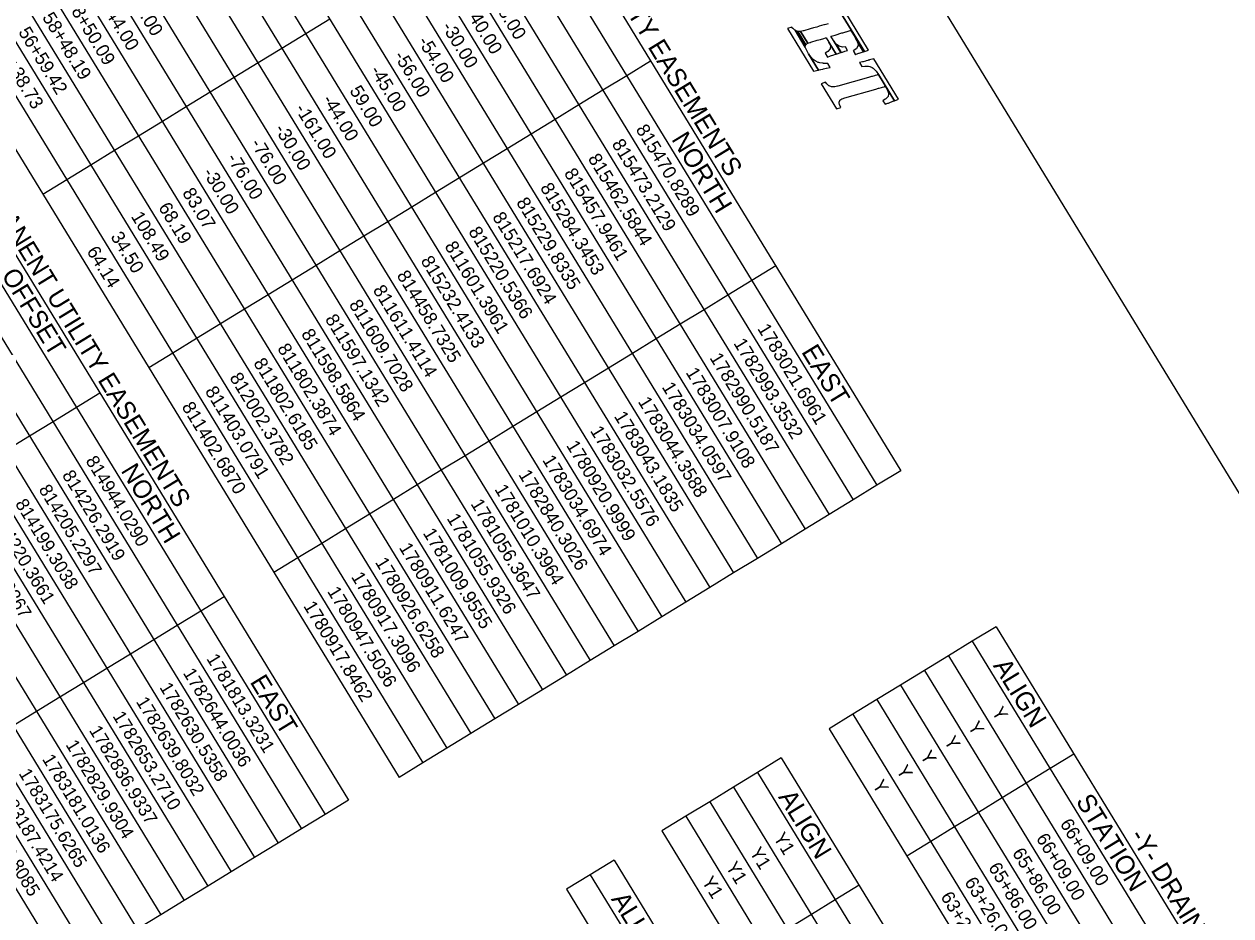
# Model space of a CAD drawing. Extents: x 1753086 to 1770987, y 792577 to 812636.
# Drawn here: x 1764623 to 1768654, y 800134 to 803112 of the extents above; entities that cross this region are included whole.
import ezdxf

# ---------------------------------------------------------------- set-up
doc = ezdxf.new("R2010")
doc.units = 0
for name, color, linetype in [('CTL Sheet Border CELL', 7, 'Continuous'), ('CTL Sheet Notes CELL', 7, 'Continuous'), ('CTL Sheet Table Cell', 7, 'Continuous'), ('CTL Sheet Text', 7, 'Continuous'), ('Sheet Data Field CELL', 7, 'Continuous')]:
    doc.layers.add(name, color=color, linetype=linetype)

msp = doc.modelspace()

# ---------------------------------------------------------------- linework, layer by layer
at = {"layer": 'CTL Sheet Border CELL'}
msp.add_lwpolyline([(1770671.7, 798289.4), (1762511, 811645.8), (1753161.6, 805933.4), (1761322.3, 792577)], close=True, dxfattribs=at)
at = {"layer": 'CTL Sheet Table Cell'}
for p, q in [((1765751, 804567), (1767551.4, 801620.3)), ((1765671.2, 804518.2), (1767471.6, 801571.5)), ((1765591.4, 804469.4), (1767391.8, 801522.7)), ((1765511.6, 804420.7), (1767312, 801474)), ((1765431.7, 804371.9), (1767232.2, 801425.2)), ((1765351.9, 804323.1), (1767152.4, 801376.4)), ((1765272.1, 804274.4), (1767072.5, 801327.6)), ((1765192.3, 804225.6), (1766992.7, 801278.9)), ((1765112.5, 804176.8), (1766912.9, 801230.1)), ((1765032.7, 804128.1), (1766833.1, 801181.3)), ((1764952.8, 804079.3), (1766753.3, 801132.6)), ((1764873, 804030.5), (1766673.5, 801083.8)), ((1764793.2, 803981.7), (1766593.6, 801035)), ((1764713.4, 803933), (1766513.8, 800986.3)), ((1764633.6, 803884.2), (1766434, 800937.5)), ((1764553.8, 803835.4), (1766354.2, 800888.7)), ((1764473.9, 803786.7), (1766274.4, 800840)), ((1764394.1, 803737.9), (1766194.6, 800791.2)), ((1764314.3, 803689.1), (1766114.7, 800742.4)), ((1764234.5, 803640.4), (1766034.9, 800693.7)), ((1764154.7, 803591.6), (1765955.1, 800644.9)), ((1764074.9, 803542.8), (1765875.3, 800596.1)), ((1763918.1, 803447), (1765706.4, 800520.1)), ((1763839.7, 803399.1), (1765628, 800472.2)), ((1763761.3, 803351.2), (1765549.6, 800424.3)), ((1763682.9, 803303.3), (1765471.2, 800376.4)), ((1763604.5, 803255.4), (1765392.8, 800328.5)), ((1763526.1, 803207.5), (1765314.4, 800280.6)), ((1763447.7, 803159.6), (1765236, 800232.7)), ((1765643.5, 803128.3), (1765563.7, 803079.5)), ((1763369.3, 803111.7), (1765157.6, 800184.8)), ((1765563.7, 803079.5), (1765483.9, 803030.7)), ((1763290.9, 803063.8), (1765079.2, 800136.9)), ((1763212.5, 803015.9), (1765000.8, 800089)), ((1765483.9, 803030.7), (1765404.1, 802982)), ((1763134.1, 802968), (1764922.4, 800041.1)), ((1765404.1, 802982), (1765324.3, 802933.2)), ((1766715.5, 802988.4), (1766635.7, 802939.6)), ((1763055.7, 802920.1), (1764844, 799993.2)), ((1765324.3, 802933.2), (1765244.4, 802884.4)), ((1766635.7, 802939.6), (1766555.9, 802890.8)), ((1765244.4, 802884.4), (1765164.6, 802835.7)), ((1766555.9, 802890.8), (1766476.1, 802842.1)), ((1762977.3, 802872.2), (1764765.6, 799945.3)), ((1766476.1, 802842.1), (1766396.3, 802793.3)), ((1765164.6, 802835.7), (1765084.8, 802786.9)), ((1765084.8, 802786.9), (1765005, 802738.1)), ((1766396.3, 802793.3), (1766316.4, 802744.5)), ((1765005, 802738.1), (1764925.2, 802689.4)), ((1766316.4, 802744.5), (1766236.6, 802695.8)), ((1764925.2, 802689.4), (1764845.4, 802640.6)), ((1766236.6, 802695.8), (1766156.8, 802647)), ((1764845.4, 802640.6), (1764765.5, 802591.8)), ((1766156.8, 802647), (1766077, 802598.2)), ((1766077, 802598.2), (1765997.2, 802549.5)), ((1764765.5, 802591.8), (1764685.7, 802543.1)), ((1765997.2, 802549.5), (1765917.4, 802500.7)), ((1765917.4, 802500.7), (1765837.5, 802451.9)), ((1765837.5, 802451.9), (1765757.7, 802403.2)), ((1765757.7, 802403.2), (1765677.9, 802354.4)), ((1765677.9, 802354.4), (1765598.1, 802305.6)), ((1765598.1, 802305.6), (1765518.3, 802256.9)), ((1767133.5, 802304.3), (1767053.7, 802255.5)), ((1765518.3, 802256.9), (1765438.5, 802208.1)), ((1767053.7, 802255.5), (1766973.9, 802206.8)), ((1765438.5, 802208.1), (1765358.6, 802159.3)), ((1766973.9, 802206.8), (1766894, 802158)), ((1765358.6, 802159.3), (1765278.8, 802110.5)), ((1766894, 802158), (1766814.2, 802109.2)), ((1765278.8, 802110.5), (1765199, 802061.8)), ((1766814.2, 802109.2), (1766734.4, 802060.5)), ((1765199, 802061.8), (1765119.2, 802013)), ((1766734.4, 802060.5), (1766654.6, 802011.7)), ((1765119.2, 802013), (1765039.4, 801964.2)), ((1766654.6, 802011.7), (1766574.8, 801962.9)), ((1766574.8, 801962.9), (1766495, 801914.2)), ((1766495, 801914.2), (1766415.1, 801865.4)), ((1764876.1, 801879.1), (1764797.7, 801831.1)), ((1764797.7, 801831.1), (1764719.3, 801783.2)), ((1766415.1, 801865.4), (1766335.3, 801816.6)), ((1766335.3, 801816.6), (1766255.5, 801767.9)), ((1764719.3, 801783.2), (1764640.9, 801735.3)), ((1766255.5, 801767.9), (1766175.7, 801719.1)), ((1764640.9, 801735.3), (1764562.5, 801687.4)), ((1766175.7, 801719.1), (1766095.9, 801670.3)), ((1766095.9, 801670.3), (1766016.1, 801621.6)), ((1766016.1, 801621.6), (1765936.2, 801572.8)), ((1767551.4, 801620.3), (1767471.6, 801571.5)), ((1765936.2, 801572.8), (1765856.4, 801524)), ((1767471.6, 801571.5), (1767391.8, 801522.7)), ((1765856.4, 801524), (1765776.6, 801475.3)), ((1767391.8, 801522.7), (1767312, 801474)), ((1765776.6, 801475.3), (1765696.8, 801426.5)), ((1767312, 801474), (1767232.2, 801425.2)), ((1765696.8, 801426.5), (1765617, 801377.7)), ((1767232.2, 801425.2), (1767152.4, 801376.4)), ((1765617, 801377.7), (1765537.2, 801329)), ((1767152.4, 801376.4), (1767072.5, 801327.6)), ((1765537.2, 801329), (1765457.3, 801280.2)), ((1767072.5, 801327.6), (1766992.7, 801278.9)), ((1766992.7, 801278.9), (1766912.9, 801230.1)), ((1766912.9, 801230.1), (1766833.1, 801181.3)), ((1765291.2, 801199.6), (1765212.8, 801151.7)), ((1765212.8, 801151.7), (1765134.4, 801103.8)), ((1766833.1, 801181.3), (1766753.3, 801132.6)), ((1765134.4, 801103.8), (1765056, 801055.9)), ((1766753.3, 801132.6), (1766673.5, 801083.8)), ((1766673.5, 801083.8), (1766593.6, 801035)), ((1767869.7, 801099.4), (1767790, 801050.7)), ((1767869.7, 801099.4), (1769688.7, 798122.3)), ((1765056, 801055.9), (1764977.6, 801008)), ((1766593.6, 801035), (1766513.8, 800986.3)), ((1767790, 801050.7), (1767710.2, 801001.9)), ((1767790, 801050.7), (1769608.9, 798073.6)), ((1764977.6, 801008), (1764899.2, 800960.1)), ((1766513.8, 800986.3), (1766434, 800937.5)), ((1767710.2, 801001.9), (1767630.5, 800953.2)), ((1767710.2, 801001.9), (1769529.2, 798024.9)), ((1764899.2, 800960.1), (1764820.9, 800912.2)), ((1767630.5, 800953.2), (1767550.7, 800904.5)), ((1767630.5, 800953.2), (1769449.5, 797976.1)), ((1764820.9, 800912.2), (1764742.5, 800864.3)), ((1766434, 800937.5), (1766354.2, 800888.7)), ((1767550.7, 800904.5), (1767471, 800855.8)), ((1767550.7, 800904.5), (1769369.7, 797927.4)), ((1764742.5, 800864.3), (1764664.1, 800816.4)), ((1766354.2, 800888.7), (1766274.4, 800840)), ((1766274.4, 800840), (1766194.6, 800791.2)), ((1767471, 800855.8), (1767391.2, 800807)), ((1767471, 800855.8), (1769290, 797878.7)), ((1764664.1, 800816.4), (1764585.7, 800768.5)), ((1766194.6, 800791.2), (1766114.7, 800742.4)), ((1767391.2, 800807), (1767311.5, 800758.3)), ((1767391.2, 800807), (1769210.2, 797830)), ((1766114.7, 800742.4), (1766034.9, 800693.7)), ((1767311.5, 800758.3), (1769130.5, 797781.2)), ((1766034.9, 800693.7), (1765955.1, 800644.9)), ((1767152, 800660.9), (1767072.3, 800612.2)), ((1767152, 800660.9), (1768971, 797683.8)), ((1768129.6, 800674.1), (1768049.8, 800625.4)), ((1765955.1, 800644.9), (1765875.3, 800596.1)), ((1768049.8, 800625.4), (1767970.1, 800576.6)), ((1767072.3, 800612.2), (1766992.5, 800563.4)), ((1767072.3, 800612.2), (1768891.3, 797635.1)), ((1766992.5, 800563.4), (1766912.8, 800514.7)), ((1766992.5, 800563.4), (1768811.5, 797586.4)), ((1767970.1, 800576.6), (1767890.3, 800527.9)), ((1765706.4, 800520.1), (1765628, 800472.2)), ((1766912.8, 800514.7), (1766833, 800466)), ((1766912.8, 800514.7), (1768731.8, 797537.6)), ((1767890.3, 800527.9), (1767810.6, 800479.2)), ((1765628, 800472.2), (1765549.6, 800424.3)), ((1766833, 800466), (1766753.3, 800417.3)), ((1766833, 800466), (1768652, 797488.9)), ((1767810.6, 800479.2), (1767730.8, 800430.5)), ((1765549.6, 800424.3), (1765471.2, 800376.4)), ((1767730.8, 800430.5), (1767651.1, 800381.7)), ((1766753.3, 800417.3), (1768572.3, 797440.2)), ((1767651.1, 800381.7), (1767571.4, 800333)), ((1765471.2, 800376.4), (1765392.8, 800328.5)), ((1765392.8, 800328.5), (1765314.4, 800280.6)), ((1766593.8, 800319.8), (1766514.1, 800271.1)), ((1766593.8, 800319.8), (1768412.8, 797342.7)), ((1765314.4, 800280.6), (1765236, 800232.7)), ((1766514.1, 800271.1), (1766434.3, 800222.4)), ((1766514.1, 800271.1), (1768333.1, 797294)), ((1765236, 800232.7), (1765157.6, 800184.8)), ((1766434.3, 800222.4), (1768253.3, 797245.3)), ((1767411.9, 800235.6), (1767332.1, 800186.9)), ((1765157.6, 800184.8), (1765079.2, 800136.9)), ((1767332.1, 800186.9), (1767252.4, 800138.1)), ((1765079.2, 800136.9), (1765000.8, 800089)), ((1767252.4, 800138.1), (1767172.6, 800089.4))]:
    msp.add_line(p, q, dxfattribs=at)
at = {"layer": 'Sheet Data Field CELL'}
msp.add_lwpolyline([(1767308.7, 803113.1), (1767300.3, 803110.8), (1767295.9, 803109.5), (1767294.5, 803109.1), (1767278.5, 803104.5), (1767276.6, 803104), (1767270.6, 803102.2), (1767259.7, 803099.1), (1767248.5, 803095.9), (1767227, 803089.8), (1767225.8, 803089.5), (1767225.4, 803089.4), (1767216.5, 803087.4), (1767240.8, 803047.7), (1767248.9, 803050.9), (1767249.3, 803051), (1767250.4, 803051.4), (1767271.8, 803057.7), (1767283, 803061), (1767293.8, 803064.2), (1767299.8, 803065.9), (1767301.7, 803066.5), (1767335.3, 803011.6), (1767351, 803016.7), (1767317.6, 803071.3), (1767318.9, 803071.7), (1767323.4, 803073), (1767331.7, 803075.5), (1767354.6, 803082.3), (1767356, 803082.7), (1767358, 803083.3), (1767367.5, 803086.1), (1767368.2, 803086.3), (1767375.7, 803088.5), (1767378.7, 803089.4), (1767378.7, 803089.4), (1767381.8, 803090.3), (1767383.2, 803090.7), (1767384.4, 803091), (1767427.7, 803020.1), (1767428.3, 803020.3), (1767429.4, 803020.6), (1767350, 803150.6)], dxfattribs=at)
for points in [[(1767364.6, 803154.6), (1767350, 803150.6), (1767429.4, 803020.6), (1767443.5, 803025.4)], [(1767187.2, 803101.7), (1767173.1, 803096.8), (1767259.9, 802954.8), (1767274.9, 802958.1), (1767275.8, 802958.4), (1767276, 802958.4), (1767242.9, 803012.7), (1767232.2, 803034.9), (1767232.2, 803035), (1767197.8, 803091.3), (1767197.7, 803091.4), (1767191.3, 803097.1), (1767190.8, 803097.5)], [(1767198.3, 803091), (1767197.9, 803091.2), (1767232.2, 803035), (1767232.3, 803035.5), (1767233.3, 803041.6), (1767234.2, 803042.6), (1767206.7, 803087.6), (1767204.7, 803088.4)], [(1767212.1, 803087.5), (1767206.8, 803087.6), (1767234.2, 803042.6), (1767237.6, 803045.9), (1767238.3, 803046.7), (1767240.8, 803047.7), (1767216.5, 803087.5), (1767213.4, 803087.5)], [(1767308, 803020), (1767298.3, 803014.4), (1767305.9, 803002), (1767316.8, 803005.6), (1767327.5, 803009.1), (1767333.4, 803011), (1767335.3, 803011.6), (1767310.6, 803052), (1767316, 803039.5), (1767315.4, 803028.8)], [(1767335.4, 803044.8), (1767327.8, 803054.6), (1767351, 803016.7), (1767352.3, 803017.1)], [(1767344.8, 803037.9), (1767335.4, 803044.8), (1767352.3, 803017.1), (1767356.7, 803018.6), (1767364.8, 803021.2), (1767373.6, 803024), (1767366.5, 803035.6), (1767356.3, 803035.3)], [(1767394.5, 803023.5), (1767392.9, 803022.3), (1767400, 803010.7), (1767401.9, 803011.4), (1767411.2, 803014.5), (1767411.9, 803014.7), (1767411.9, 803014.8), (1767419.3, 803017.2), (1767422.2, 803018.2), (1767425.2, 803019.2), (1767426.6, 803019.7), (1767406.7, 803052.3), (1767407.3, 803048.4), (1767408.8, 803040.2), (1767407.1, 803037.1), (1767403, 803029.4), (1767402.3, 803029)], [(1767400.1, 803065.3), (1767406.7, 803052.3), (1767426.6, 803019.7), (1767427.7, 803020.1)], [(1767255.9, 802996), (1767242.9, 803012.7), (1767276, 802958.4), (1767278.6, 802959), (1767278.6, 802959), (1767279, 802959.1), (1767283.1, 802960), (1767284.5, 802960.3), (1767289.2, 802961.4), (1767290.3, 802961.6), (1767293.1, 802962.2), (1767301.9, 802964.2), (1767302.3, 802964.3), (1767303.5, 802964.5), (1767303.5, 802964.6), (1767315.4, 802967.2), (1767307.7, 802979.9), (1767293.6, 802980.7), (1767292.2, 802980.8), (1767291.7, 802980.9), (1767280.4, 802982.9), (1767276.9, 802983.5), (1767275.5, 802983.7), (1767267.5, 802988.2), (1767265.1, 802989.5), (1767258, 802993.4), (1767256.3, 802995.6)], [(1767392.9, 803022.3), (1767398.6, 803010.2), (1767400, 803010.7)], [(1767423, 802985.8), (1767413.7, 802983.2), (1767421.5, 802970.5), (1767431.5, 802971.8), (1767434.1, 802971.8), (1767443.7, 802971.5), (1767447.7, 802970.1), (1767447.7, 802970.2), (1767455.5, 802967.5), (1767458.8, 802964.5), (1767466, 802957.8), (1767468.6, 802954.2), (1767476.7, 802943.2), (1767530, 802855.9), (1767543.9, 802861.2), (1767461.2, 802996.4), (1767446.7, 802992.3), (1767445.5, 802992), (1767445.1, 802991.9), (1767442.5, 802991.2), (1767441.3, 802990.8), (1767436, 802989.4), (1767433.2, 802988.6), (1767425.2, 802986.4)], [(1767299.6, 802917.7), (1767285.4, 802912.9), (1767336.6, 802829.2), (1767351.2, 802833.2), (1767347.2, 802841.6), (1767346.6, 802842.8), (1767345.4, 802849.7), (1767345.2, 802851.4), (1767347.5, 802857.3), (1767347.7, 802857.7), (1767354.3, 802862), (1767354.9, 802862.4), (1767364, 802865.5), (1767364.5, 802865.6), (1767467.6, 802894.9), (1767476.8, 802897.6), (1767479, 802898.2), (1767487.1, 802900.5), (1767489.8, 802901.3), (1767495.1, 802902.8), (1767496.3, 802903.1), (1767498.9, 802903.9), (1767499.3, 802904), (1767500.4, 802904.3), (1767529.9, 802855.9), (1767530, 802855.9), (1767476.7, 802943.2), (1767476.6, 802943.2), (1767475.5, 802942.9), (1767475.2, 802942.8), (1767472.5, 802942), (1767471.3, 802941.7), (1767466, 802940.2), (1767463.3, 802939.4), (1767455.3, 802937.1), (1767453.1, 802936.5), (1767443.8, 802933.9), (1767340.7, 802904.6), (1767340.2, 802904.4), (1767330.5, 802902.3), (1767329.8, 802902.1), (1767320.4, 802902.2), (1767320, 802902.2), (1767312.1, 802905.5), (1767311.1, 802905.9), (1767304.4, 802911.9), (1767304, 802912.2)], [(1767499.4, 802860.7), (1767491.6, 802855.8), (1767498.7, 802844.1), (1767507.5, 802847.4), (1767509.6, 802848.2), (1767517.2, 802851.1), (1767519.8, 802852.1), (1767519.8, 802852.1), (1767524.9, 802854), (1767526, 802854.4), (1767526, 802854.4), (1767528.6, 802855.4), (1767528.9, 802855.5), (1767529.9, 802855.9), (1767500.4, 802904.3), (1767506.2, 802892.7), (1767506.7, 802891.2), (1767509.9, 802880.9), (1767509.6, 802879), (1767508.5, 802870.6), (1767506.7, 802868.4), (1767501.3, 802861.9)]]:
    msp.add_lwpolyline(points, close=True, dxfattribs=at)

# ---------------------------------------------------------------- texts
at = {"layer": 'CTL Sheet Notes CELL'}
for s, height, p in [('-Y- PERMANENT UTILITY EASEMENTS', 62.357, (1766175.4, 803902.2)), ('-Y1- PERMANENT UTILITY EASEMENTS', 61.25, (1764323.6, 802812.6)), ('NORTH', 62.36, (1766783.6, 802727.5)), ('OFFSET', 61.25, (1764545.4, 802273.5)), ('EAST', 62.36, (1767217.5, 802017.4)), ('NORTH', 61.25, (1764944.4, 801620.4)), ('ALIGN', 62.3, (1767858, 800969.2)), ('EAST', 61.25, (1765375.4, 800915)), ('ALIGN', 62.3, (1767140.3, 800530.7)), ('STATION', 62.3, (1768134.3, 800516.9)), ('-Y- DRAINAGE UTILITY EASEMENTS', 62.3, (1768314.5, 800401.3)), ('ALIGN', 62.3, (1766582.1, 800189.6))]:
    msp.add_text(s, height=height, rotation=301.4249, dxfattribs=at).set_placement(p)
at = {"layer": 'CTL Sheet Text'}
for s, height, p in [('60+44.00', 44.54, (1764921.4, 803280.8)), ('60+44.00', 44.54, (1764841.5, 803232)), ('58+50.09', 44.54, (1764761.7, 803183.3)), ('58.00', 44.54, (1766187.2, 803182.5)), ('58+48.19', 44.54, (1764681.9, 803134.5)), ('40.00', 44.54, (1766107.4, 803133.7)), ('56+59.42', 44.54, (1764602.1, 803085.7)), ('-30.00', 44.54, (1766016.1, 803103.6)), ('62+38.73', 44.54, (1764522.3, 803037)), ('-54.00', 44.54, (1765936.3, 803054.8)), ('-56.00', 44.54, (1765856.5, 803006.1)), ('-45.00', 44.54, (1765776.7, 802957.3)), ('59.00', 44.54, (1765708.3, 802889.9)), ('-161.00', 44.54, (1765525.9, 802829.6)), ('-44.00', 44.54, (1765617.1, 802859.8)), ('-30.00', 44.54, (1765457.4, 802762.2)), ('815470.8289', 44.541, (1766664.3, 802760.5)), ('-76.00', 44.54, (1765377.6, 802713.5)), ('815473.2129', 44.541, (1766584.4, 802711.7)), ('815462.5844', 44.541, (1766504.6, 802662.9)), ('-76.00', 44.54, (1765297.8, 802664.7)), ('-30.00', 44.54, (1765218, 802615.9)), ('815457.9461', 44.541, (1766424.8, 802614.2)), ('83.07', 44.54, (1765149.6, 802548.5)), ('815284.3453', 44.541, (1766345, 802565.4)), ('68.19', 44.54, (1765069.7, 802499.7)), ('815229.8335', 44.541, (1766265.2, 802516.6)), ('108.49', 44.54, (1764978.5, 802469.6)), ('815217.6924', 44.541, (1766185.4, 802467.8)), ('815220.5366', 44.541, (1766105.5, 802419.1)), ('34.50', 44.54, (1764910.1, 802402.2)), ('64.14', 44.54, (1764830.3, 802353.4)), ('811601.3961', 44.541, (1766025.7, 802370.3)), ('815232.4133', 44.541, (1765945.9, 802321.5)), ('814458.7325', 44.541, (1765866.1, 802272.8)), ('811611.4114', 44.541, (1765786.3, 802224)), ('811609.7028', 44.541, (1765706.5, 802175.2)), ('811597.1342', 44.541, (1765626.6, 802126.5)), ('811598.5864', 44.541, (1765546.8, 802077.7)), ('1783021.6961', 44.541, (1767070.8, 802095)), ('811802.3874', 44.541, (1765467, 802028.9)), ('1782993.3532', 44.541, (1766991, 802046.3)), ('811802.6185', 44.541, (1765387.2, 801980.2)), ('1782990.5187', 44.541, (1766911.2, 801997.5)), ('1783007.9108', 44.541, (1766831.4, 801948.7)), ('812002.3782', 44.541, (1765307.4, 801931.4)), ('1783034.0597', 44.541, (1766751.6, 801900)), ('811403.0791', 44.541, (1765225.6, 801885.9)), ('811402.6870', 44.541, (1765147.7, 801833.9)), ('1783044.3588', 44.541, (1766671.7, 801851.2)), ('1783043.1835', 44.541, (1766591.9, 801802.4)), ('1783032.5576', 44.541, (1766512.1, 801753.7)), ('1780920.9999', 44.541, (1766432.3, 801704.9)), ('814944.0290', 43.75, (1764826.7, 801653.6)), ('1783034.6974', 44.541, (1766352.5, 801656.1)), ('814226.2919', 43.75, (1764748.3, 801605.7)), ('1782840.3026', 44.541, (1766272.7, 801607.4)), ('814205.2297', 43.75, (1764669.9, 801557.8)), ('1781010.3964', 44.541, (1766192.8, 801558.6)), ('814199.3038', 43.75, (1764591.5, 801509.9)), ('1781056.3647', 44.541, (1766113, 801509.8)), ('814220.3661', 43.75, (1764513.1, 801462)), ('1781055.9326', 44.541, (1766033.2, 801461.1)), ('814102.9267', 43.75, (1764434.7, 801414.1)), ('1781009.9555', 44.541, (1765953.4, 801412.3)), ('1780911.6247', 44.541, (1765873.6, 801363.5)), ('1780926.6258', 44.541, (1765793.8, 801314.8)), ('1780917.3096', 44.541, (1765713.9, 801266)), ('1780947.5036', 44.541, (1765634.1, 801217.2)), ('1780917.8462', 44.541, (1765554.3, 801168.5)), ('1781813.3231', 43.75, (1765230.5, 800992.7)), ('1782644.0036', 43.75, (1765152.1, 800944.8)), ('1782630.5358', 43.75, (1765073.7, 800896.9)), ('1782639.8032', 43.75, (1764995.3, 800849)), ('Y', 44.5, (1767853.4, 800814.6)), ('1782653.2710', 43.75, (1764916.9, 800801.1)), ('Y', 44.5, (1767773.6, 800765.9)), ('1782836.9337', 43.75, (1764838.5, 800753.2)), ('1782829.9304', 43.75, (1764760.1, 800705.3)), ('Y', 44.5, (1767693.9, 800717.2)), ('1783181.0136', 43.75, (1764681.7, 800657.4)), ('Y', 44.5, (1767614.1, 800668.4)), ('1783175.6265', 43.75, (1764603.3, 800609.4)), ('Y', 44.5, (1767534.4, 800619.7)), ('Y', 44.5, (1767454.6, 800571)), ('1783187.4214', 43.75, (1764524.9, 800561.5)), ('1783192.8085', 43.75, (1764446.6, 800513.6)), ('66+09.00', 44.5, (1768081.4, 800441.4)), ('Y1', 44.5, (1767124.2, 800394.9)), ('66+09.00', 44.5, (1768001.6, 800392.7)), ('Y1', 44.5, (1767044.4, 800346.2)), ('65+86.00', 44.5, (1767921.9, 800344)), ('Y1', 44.5, (1766964.7, 800297.5)), ('65+86.00', 44.5, (1767842.1, 800295.3)), ('Y1', 44.5, (1766884.9, 800248.8)), ('63+26.00', 44.5, (1767762.4, 800246.5)), ('63+26.00', 44.5, (1767682.7, 800197.8))]:
    msp.add_text(s, height=height, rotation=301.4249, dxfattribs=at).set_placement(p)

doc.saveas('drawing.dxf')
